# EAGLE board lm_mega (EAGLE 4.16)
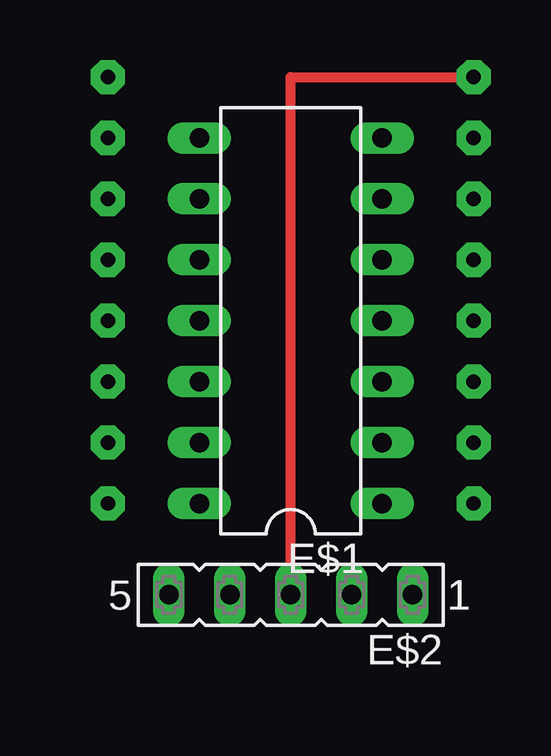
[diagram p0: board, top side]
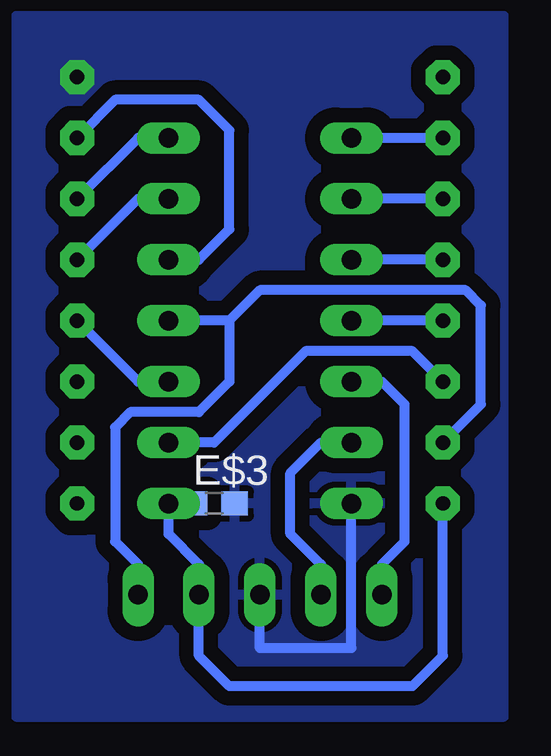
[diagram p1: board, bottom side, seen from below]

No outline drawn. Coordinates in mm, seen from the top.
Copper layers (1*16): Top 0.035mm / dielectric 1.5mm / Bottom 0.035mm
Design rules "default": minimum track width 10mil, minimum drill 24mil, track to track 8mil, track to pad 8mil, pad to pad 8mil, via to via 8mil, smd to smd 8mil, copper to edge 40mil, drill to drill 8mil, minimum pad ring 10mil, minimum via ring 8mil, stop-mask expansion 4mil, vias tented up to drill 0mil, thermal gap 10mil

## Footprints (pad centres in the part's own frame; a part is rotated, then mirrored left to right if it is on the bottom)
DIL14 = drill 0.813 long: 1 -7.62,-3.81; 2 -5.08,-3.81; 3 -2.54,-3.81; 4 0,-3.81; 5 2.54,-3.81; 6 5.08,-3.81; 7 7.62,-3.81; 8 7.62,3.81; 9 5.08,3.81; 10 2.54,3.81; 11 0,3.81; 12 -2.54,3.81; 13 -5.08,3.81; 14 -7.62,3.81
FE05-1 = drill 0.813 long: 1 -5.08,0; 2 -2.54,0; 3 0,0; 4 2.54,0; 5 5.08,0
C0603 = smd 1.1 x 1: 1 -0.85,0; 2 0.85,0

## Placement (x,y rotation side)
E$1  [DIL14]  10.16,16.51 90 top
E$2  [FE05-1]  10.16,5.08 180 top
E$3  [C0603]  12.06,8.89 0 bottom

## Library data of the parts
E$1 = microchip-5
E$2 = con-lsta
E$3 = rcl

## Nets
GND: E$1.14 E$2.3 E$3.2
S$5: E$1.6
S$6: E$1.7
S$7: E$1.5
S$8: E$1.8
S$9: E$1.9
S$10: E$1.10
S$11: E$1.11
S$12: E$1.12 E$2.5
S$13: E$1.3
S$14: E$1.1 E$2.2
S$15: E$1.4 E$2.1
S$17: E$1.13 E$2.4

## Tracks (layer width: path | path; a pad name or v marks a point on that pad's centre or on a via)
GND  (via drill 0.6 pad 1.42)
  Top 0.406: v17.78,26.67 10.16,26.67 E$2.3
  Bottom 0.406: E$2.3 10.16,2.86 6.35,2.86 E$1.14
  pour Bottom (isolate 0.61): 0,0 0,29.21 20.32,29.21 20.32,0
S$1  (via drill 0.6 pad 1.42)
  other vias: 17.78,8.89
S$2  (via drill 0.6 pad 1.42)
  other vias: 17.78,24.13
S$3  (via drill 0.6 pad 1.42)
  other vias: 17.78,13.97
S$5  (via drill 0.6 pad 1.42)
  Bottom 0.406: E$1.6 15.24,21.59 v17.78,19.05
S$6  (via drill 0.6 pad 1.42)
  Bottom 0.406: E$1.7 15.24,24.13 v17.78,21.59
S$7
  Bottom 0.406: 17.78,24.13 16.19,25.72 12.7,25.72 11.43,24.45 11.43,20.32 12.7,19.05 E$1.5
S$8  (via drill 0.6 pad 1.42)
  Bottom 0.406: v2.54,24.13 E$1.8
S$9  (via drill 0.6 pad 1.42)
  Bottom 0.406: v2.54,21.59 E$1.9
S$10  (via drill 0.6 pad 1.42)
  Bottom 0.406: v2.54,19.05 E$1.10
S$11  (via drill 0.6 pad 1.42)
  Bottom 0.406: v2.54,16.51 E$1.11
S$12
  Bottom 0.406: E$1.12 5.08,13.97 4.13,13.02 4.13,7.3 5.08,6.35 E$2.5
S$13  (via drill 0.6 pad 1.42)
  Bottom 0.406: E$1.3 15.24,13.97 v17.78,16.51
S$14  (via drill 0.6 pad 1.42)
  Bottom 0.406: v2.54,8.89 2.54,2.54 3.81,1.27 11.43,1.27 12.7,2.54 12.7,6.35 | 12.7,6.35 13.97,7.62 E$1.1 | 12.7,6.35 E$2.2
S$15  (via drill 0.6 pad 1.42)
  Bottom 0.406: v2.54,11.43 0.95,13.02 0.95,17.14 1.59,17.78 10.16,17.78 11.43,16.51 | 11.43,16.51 E$1.4 | 11.43,16.51 11.43,13.97 12.7,12.7 15.56,12.7 16.19,12.06 16.19,7.3 15.24,6.35 E$2.1
S$16  (via drill 0.6 pad 1.42)
  other vias: 2.54,26.67
S$17
  Bottom 0.406: E$1.13 7.62,11.43 8.89,10.16 8.89,7.62 7.62,6.35 E$2.4
S$19  (via drill 0.6 pad 1.42)
  other vias: 17.78,11.43
S$20  (via drill 0.6 pad 1.42)
  Bottom 0.406: 13.97,11.43 12.06,11.43 8.26,15.24 3.81,15.24 v2.54,13.97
